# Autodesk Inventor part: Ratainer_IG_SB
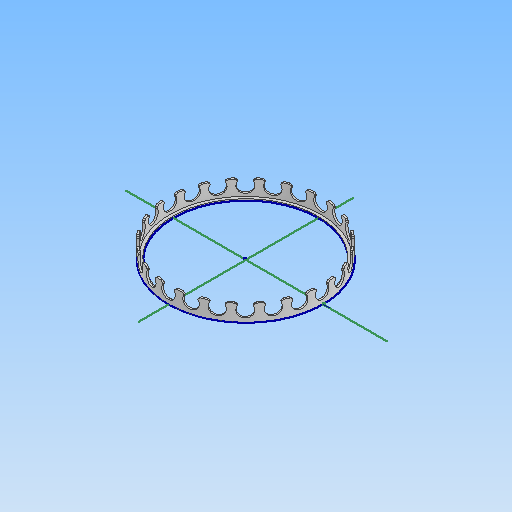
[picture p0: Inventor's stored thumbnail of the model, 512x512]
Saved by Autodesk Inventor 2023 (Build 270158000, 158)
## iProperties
Created: 2024-05
Part Number: Ratainer_IG_SB
Material: 一般
Document SubType Name: Modeling
Designer: kumagai
Density: 1 g/cm^3
Appearance: 既定
Author: kumagai
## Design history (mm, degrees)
derived "CoreSketch.ipt"
  sketch "Vertical"
    geometry: L1 (0, 65.337)-(0, -65.337) reference; L2 (-46.2, 0)-(46.2, 0) reference; L3 (-11, 2)-(11, 2) reference; L4 (11, 2)-(11, -2) reference; L5 (11, -2)-(-11, -2) reference; L6 (-11, -2)-(-11, 2) reference; L7 (11, 2)-(33, 2) reference; L8 (33, 2)-(33, -2) reference; L9 (33, -2)-(11, -2) reference; L10 (11, -2)-(11, 2) reference; L11 (22, 2.772)-(22, -2.683) reference; L12 (-33, 2)-(-11, 2) reference; L13 (-11, 2)-(-11, -2) reference; L14 (-11, -2)-(-33, -2) reference; L15 (-33, -2)-(-33, 2) reference; L16 (-22, 4.087)-(-22, -4.199) reference; L17 (-33, 10)-(-11, 10) reference; L18 (-11, 10)-(-11, 6) reference; L19 (-11, 6)-(-33, 6) reference; L20 (-33, 6)-(-33, 10) reference; L21 (-27.353, 10)-(-16.647, 10) reference; L22 (-16.647, 10)-(-16.647, 16) reference; L23 (-16.647, 16)-(-27.353, 16) reference; L24 (-27.353, 16)-(-27.353, 10) reference; L25 (11, 16)-(33, 16) reference; L26 (33, 16)-(33, 12) reference; L27 (33, 12)-(11, 12) reference; L28 (11, 12)-(11, 16) reference; L29 (16.134, 12)-(27.866, 12) reference; L30 (27.866, 12)-(27.866, 6) reference; L31 (27.866, 6)-(16.134, 6) reference; L32 (16.134, 6)-(16.134, 12) reference; L33 (-22, 18.272)-(-22, 9.031) reference; L34 (22, 22.635)-(22, 12.71) reference; L35 (33, -2)-(35, -2) reference; L36 (35, -2)-(35, 10) reference; L37 (35, 10)-(33, 10) reference; L38 (33, 10)-(33, -2) reference; L39 (0, -4)-(37.5, -4) reference; L40 (40.5, -1)-(40.5, 14) reference; L41 (43.9, -8)-(0, -8) reference; L42 (0, -4)-(0, -8) reference; L43 (35, -2)-(39, -2) reference; L44 (39, -2)-(39, 3.066) reference; L45 (38.45, 8.685)-(41.471, 10.429) reference; L46 (38.45, 10)-(35, 10) reference; L47 (40.5, 9.627)-(41.993, 8.375) reference; L48 (41.55, 3.315)-(40.5, 2.709) reference; L49 (37.5, -4)-(40.5, -1) reference; L50 (-43, 43.294)-(-1, 43.294) reference; L51 (-1, 43.294)-(-1, 26) reference; L52 (-1, 26)-(-43, 26) reference; L53 (-43, 26)-(-43, 43.294) reference; L54 (1, 43.294)-(43, 43.294) reference; L55 (43, 43.294)-(43, 26) reference; L56 (43, 26)-(1, 26) reference; L57 (1, 26)-(1, 43.294) reference; L58 (-22, 45.556)-(-22, 31.232) reference; L59 (22, 47.214)-(22, 32.287) reference; L60 (48, 5.268)-(48, -2.616) reference; L61 (43.6, -11)-(54, -11) reference; L62 (54, -11)-(54, 18) reference; L63 (45.222, -3.461)-(46.5, -2.566) reference; L64 (48, -2.616)-(49.192, -3.808) reference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; A1 r 3.1 centre (40, 6) between (39, 3.066) and (38.45, 8.685) reference; A2 r 3.1 centre (47, -6) between (45.222, -3.461) and (49.192, -3.808) reference; A3 r 3.1 centre (47, 13) between (43.9, 13) and (49, 10.631) reference; 2 further points; 1 other entity
    constraints: 1 other
sketch "スケッチ3" dims "d3" = 0.9
  geometry: L1 (0, -56)-(0, 56) reference; C1 r 37.6 at (0, 0); 13 further points
  constraints: 3 coincident, 2 horizontal alignment, 1 centre point, 7 other
  dimensions: "d1" = 38.45 distance from line of point (-38.45, 0) L1 (derived); "d2" = 40.5 distance from line of point (-40.5, 0) L1 (derived); "d4" = 0.5 distance of point (-40.5, 0) point (-40, 0); "d5" = 0.65 distance of point (-38.45, 0) point (-39.1, 0) (derived); "d10" = 1.5 dimension on C1
extrude "押し出し1" new body sketch "スケッチ3" distance "d6" = 8.5; taper "d7" = 0 deg
sketch "スケッチ4"
  geometry: L1 (8.5, -40)-(8.5, 40) reference; L2 (0, -40)-(0, 40) reference; L3 (0, 56)-(0, -56) reference; L4 (-24.112, 0)-(59.102, 0) reference; L5 (8.5, 4)-(8.5, -4); L6 (8.5, -4)-(7.906, -3.173); L7 (7.906, 3.173)-(8.5, 4); A1 r 3.5 centre (5.5, 0) between (7.25, 3.031) and (7.25, -3.031); A2 r 0.5 centre (7.5, 3.464) between (7.25, 3.031) and (7.906, 3.173); A3 r 0.5 centre (7.5, -3.464) between (7.906, -3.173) and (7.25, -3.031); 3 further points
  constraints: 6 end point, 6 point on circle, 4 tangent, 3 centre point, 1 equal radius, 1 point on line, 1 symmetric about line, 1 vertical alignment
  dimensions: "d9" = 5.5 distance from line of A1.centre L2; "d13" = 0.5 radius of A2; "d19" = 3.5 radius of A1; "d21" = 8.5 distance between parallel lines of L2 L5; "d22" = 4 distance from line of L5.end L4; "d23" = 3 distance from line of A1.centre L5 (derived); "d24" = 2 horizontal distance of A3.centre A1.centre; "d25" = 6.9282 distance of A3.centre A2.centre (derived); "d26" = 5.9282 dimension on A3 A2 (derived)
extrude "押し出し2" join sketch "スケッチ3" distance "d11" = 0.6; taper "d12" = 0 deg
extrude "押し出し3" cut sketch "スケッチ4" extent not by distance; stored distance "d14" = 0; taper "d15" = 0 deg
pattern_circular "円形状パターン1" dims angle "d17" = 180 deg
node "ソリッド1"
